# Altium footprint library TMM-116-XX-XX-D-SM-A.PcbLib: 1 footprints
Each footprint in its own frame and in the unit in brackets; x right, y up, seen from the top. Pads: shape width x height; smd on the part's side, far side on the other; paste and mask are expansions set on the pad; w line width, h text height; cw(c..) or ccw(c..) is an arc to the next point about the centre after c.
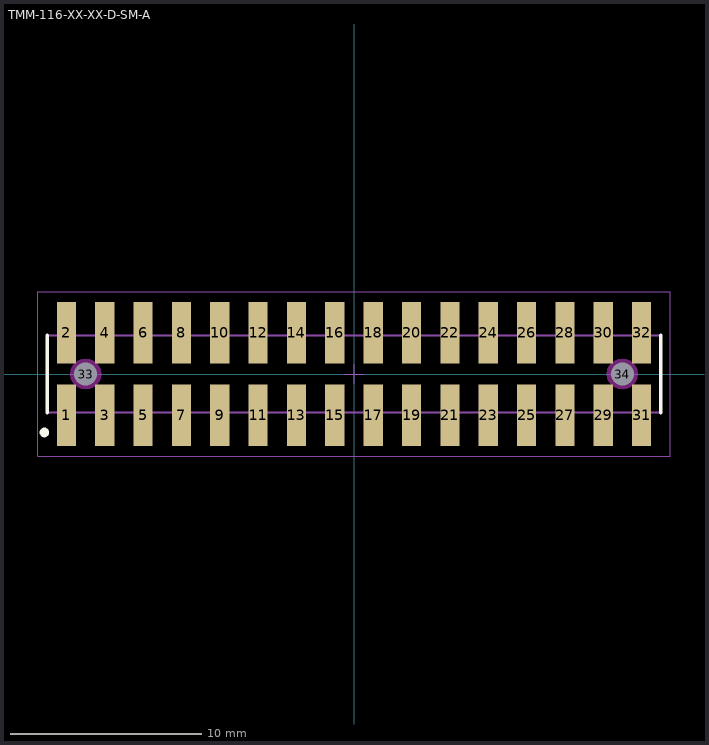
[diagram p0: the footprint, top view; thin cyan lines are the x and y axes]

## TMM-116-XX-XX-D-SM-A [mm] "2.00mm pitch, 32 pin, terminal strip; double row, w/alignment pins, SMT"
height 2.77
pads (34):
  rect 1x3.2 smd mask+0: 1(-15,-2.15) 2(-15,2.15) 3(-13,-2.15) 4(-13,2.15) 5(-11,-2.15) 6(-11,2.15) 7(-9,-2.15) 8(-9,2.15) 9(-7,-2.15) 10(-7,2.15) 11(-5,-2.15) 12(-5,2.15) 13(-3,-2.15) 14(-3,2.15) 15(-1,-2.15) 16(-1,2.15) 17(1,-2.15) 18(1,2.15) 19(3,-2.15) 20(3,2.15) 21(5,-2.15) 22(5,2.15) 23(7,-2.15) 24(7,2.15) 25(9,-2.15) 26(9,2.15) 27(11,-2.15) 28(11,2.15) 29(13,-2.15) 30(13,2.15) 31(15,-2.15) 32(15,2.15)
  round 1 hole 1.2 unplated mask+0: 33(-14,0) 34(14,0)
Top Overlay:
  circle w0.25: c-16.15,-3.05 r0.125
  lines w0.2: -16,-2 -16,2 ; 16,-2 16,2
Keep-Out Layer:
  pour cut-out: -13.193,0 -13.221,0.209 -13.301,0.403 -13.429,0.571 -13.597,0.699 -13.791,0.779 -14,0.807 -14.209,0.779 -14.403,0.699 -14.571,0.571 -14.699,0.403 -14.779,0.209 -14.807,0 -14.779,-0.209 -14.699,-0.403 -14.571,-0.571 -14.403,-0.699 -14.209,-0.779 -14,-0.807 -13.791,-0.779 -13.597,-0.699 -13.429,-0.571 -13.301,-0.403 -13.221,-0.209
  pour cut-out: 14.807,0 14.779,0.209 14.699,0.403 14.571,0.571 14.403,0.699 14.209,0.779 14,0.807 13.791,0.779 13.597,0.699 13.429,0.571 13.301,0.403 13.221,0.209 13.193,0 13.221,-0.209 13.301,-0.403 13.429,-0.571 13.597,-0.699 13.791,-0.779 14,-0.807 14.209,-0.779 14.403,-0.699 14.571,-0.571 14.699,-0.403 14.779,-0.209
Mechanical 12:
  lines w0.001: -16,-2 16,-2 16,2 -16,2 -16,-2
Mechanical 13:
  lines w0.1: -16,-2 16,-2 16,2 -16,2 -16,-2
  text ".Designator" at 0,-0.127 h1.52
Mechanical 15:
  lines w0.05: -0.5,0 0.5,0 ; 0,-0.5 0,0.5 ; -16.5,-4.3 16.5,-4.3 16.5,4.3 -16.5,4.3 -16.5,-4.3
